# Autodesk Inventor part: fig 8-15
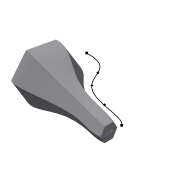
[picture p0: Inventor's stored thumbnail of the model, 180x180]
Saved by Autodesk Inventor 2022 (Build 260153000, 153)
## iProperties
Created: 2004-05
Part Number: fig 8-15
Document SubType Name: Modeling
Designer: CADCIM Technologies
Manufacturer: Standard
Standards Organization: Custom
Density: 1 g/cm^3
Material: Generic
Appearance: Default
Author: CADCIM Technologies
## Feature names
1. Sweep7
## Parameters: d6 = 0, d7 = 0
